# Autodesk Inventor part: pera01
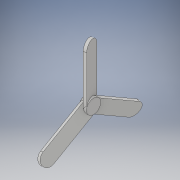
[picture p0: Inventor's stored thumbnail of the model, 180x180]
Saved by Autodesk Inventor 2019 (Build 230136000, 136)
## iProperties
Created: 2020-08
Part Number: pera01
Material: 一般
Document SubType Name: Modeling
Designer: kikut
Density: 1 g/cm^3
Appearance: 既定
Author: kikut
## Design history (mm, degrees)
sketch "スケッチ3"
  geometry: L1 (0.005, -0.009)-(-0.001, 0.01); L2 (-0.001, 0.01)-(-0.005, 0.009); L3 (-0.005, 0.009)-(0.001, -0.01); L4 (0.001, -0.01)-(0.005, -0.009); L5 (0.005, -0.009)-(-0.005, 0.009); L6 (-0.001, 0.01)-(0.001, -0.01); L7 (0, -0.014)-(0, 0.014) reference; 3 further points
  constraints: 12 end point, 3 midpoint, 2 parallel, 1 coincident, 1 perpendicular
  dimensions: "d8" = 0.02 distance of L1.start L1.end; "d9" = 15 deg angle of L7 L1; "d19" = 0.004 distance of L3.end L1.start
extrude "押し出し1" new body sketch "スケッチ3" distance "d10" = 0.079; taper "d11" = 0 deg
fillet "フィレット1" dims "d12" = 0.01
pattern_circular "円形状パターン1" dims "d14" = 360 deg
sketch "スケッチ5"
  geometry: C1 r 0.01 at (0, 0); 1 further point
  constraints: 1 centre point, 1 coincident
  dimensions: "d16" = 0.02 diameter of C1
extrude "押し出し2" join sketch "スケッチ5" stored distance "d17" = 0.01; taper "d18" = 0 deg
node "ソリッド1"
